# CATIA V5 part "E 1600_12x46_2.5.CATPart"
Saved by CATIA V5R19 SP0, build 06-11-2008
Part number: E 1600_12x46_2.5
Nomenclature: E 1600_12x46_2.5
Source: Unknown
Description: PART-E 1600_12x46_2.5-DESC
Bounding box of the stored display mesh (mm): x -14 to 14, y -14 to 14, z 0 to 40.1
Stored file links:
  C:\Users\jsmid\Desktop\DP_Smidak_Forma LEGO\E 1600_12x46_2.5.CATPart
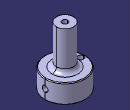
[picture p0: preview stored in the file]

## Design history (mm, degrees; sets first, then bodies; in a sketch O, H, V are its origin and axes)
Body1 "E 1600_12x46_2.5" (main body)
  Solid1: solid without history
  Sketch1 on face of Solid1, origin (0, 0, 42), H (1, 0, 0), V (0, 1, 0)
    circle A1 centre (0, 0) radius 7.6529
  Pocket1: profile Sketch1, direction (0, 0, -1), length 1.9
